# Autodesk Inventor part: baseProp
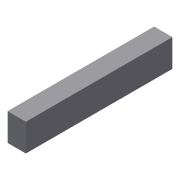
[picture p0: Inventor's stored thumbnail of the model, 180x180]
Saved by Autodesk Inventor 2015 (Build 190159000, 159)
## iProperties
Created: 2016-08
Part Number: baseProp
Material: EIFS, Exterior Insulation
Document SubType Name: Modeling
Designer: user
Density: 0.023 g/cm^3
Appearance: Gray
Author: user
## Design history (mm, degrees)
sketch "Sketch1"
  geometry: L1 (0, 6.179)-(6.35, 6.179); L2 (6.35, 6.179)-(6.35, 15.704); L3 (6.35, 15.704)-(0, 15.704); L4 (0, 15.704)-(0, 6.179); 1 further point
  constraints: 8 end point, 2 parallel, 1 horizontal, 1 perpendicular
  dimensions: "d0" = 6.35 distance of L3.end L2.end; "d1" = 9.525 distance of L2.end L1.end
workplane "Work Plane1"
extrude "Extrusion1" new body sketch "Sketch1" stored distance "d2" = 25.4; taper "d3" = 0 deg
body "Solid1"
